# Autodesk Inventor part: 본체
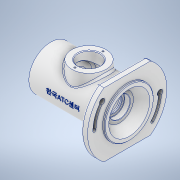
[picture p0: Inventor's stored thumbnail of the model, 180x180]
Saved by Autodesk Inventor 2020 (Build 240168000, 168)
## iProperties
Created: 2022-05
Part Number: 본체
Material: 알루미늄 6061
Document SubType Name: Modeling
Designer: Student
Density: 2.7 g/cm^3
Appearance: 알루미늄 - 평지
Mass: 692.617 g
Surface Area: 620.9 cm^2
Volume: 256.525 cm^3
Author: Student
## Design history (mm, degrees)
sketch "스케치3"
  geometry: L1 (47, 33.985)-(47, -33.985); L2 (-47, 33.985)-(-47, -33.985); A1 r 58 centre (0, 0) between (47, 33.985) and (-47, 33.985); A2 r 58 centre (0, 0) between (-47, -33.985) and (47, -33.985); 1 further point
  constraints: 4 end point, 4 point on circle, 2 centre point, 1 coincident, 1 parallel, 1 vertical
  dimensions: "d1" = 94 distance between parallel lines of L2 L1; "d2" = 47 horizontal distance of L1.start point (0, 0); "d3" = 58 radius of A2; "d4" = 58 radius of A1
extrude "돌출1" new body sketch "스케치3" distance "d5" = 10; taper "d6" = 0 deg
sketch "스케치4"
  geometry: C1 r 32 at (0, 0); 1 further point
  constraints: 1 centre point, 1 coincident
  dimensions: "d7" = 32 radius of C1
extrude "돌출2" join sketch "스케치4" distance "d8" = 102; taper "d9" = 0 deg
sketch "스케치6"
  geometry: C1 r 36 at (0, 0); 1 further point
  constraints: 1 centre point, 1 coincident
  dimensions: "d25" = 72 diameter of C1
extrude "돌출3" join sketch "스케치6" distance "d26" = 3; taper "d27" = 0 deg
sketch "스케치7"
  geometry: L1 (-118.309, 0)-(16.901, 0); L2 (0, -47)-(-10, -47) reference; L3 (-104, 0)-(-104, 24); L4 (-104, 24)-(-101, 24); L5 (-101, 24)-(-101, 22.5); L6 (-101, 22.5)-(-90, 22.5); L7 (-90, 22.5)-(-90, 17.5); L8 (-90, 17.5)-(-88.25, 17.5); L9 (-88.25, 17.5)-(-88.25, 18.5); L10 (-88.25, 18.5)-(-86, 18.5); L11 (-86, 18.5)-(-86, 17.5); L12 (-86, 17.5)-(-75, 17.5); L13 (-75, 17.5)-(-75, 27); L14 (-75, 27)-(-37, 27); L15 (3, -36)-(3, 36) reference; L16 (-26, 15)-(-21, 15); L17 (-21, 15)-(-21, 11); L18 (-21, 11)-(-19, 11); L19 (-19, 11)-(-19, 15); L20 (-11, 20)-(3, 30); L21 (-37, 27)-(-37, 17.5); L22 (-37, 17.5)-(-26, 17.5); L23 (-26, 17.5)-(-26, 15); L24 (-19, 15)-(-11.7, 15); L25 (-11.7, 15)-(-11, 15); L26 (-11, 15)-(-11, 20); 2 further points
  constraints: 48 end point, 14 perpendicular, 4 horizontal, 4 point on line, 3 vertical
  dimensions: "d28" = 47 distance between parallel lines of L2 L1; "d29" = 3 distance of L3.end L4.end; "d30" = 11 distance of L5.end L6.end; "d31" = 48 diameter of L4 L1; "d32" = 45 diameter of L6 L1; "d33" = 35 diameter of L8 L1; "d34" = 4 horizontal distance of L10.end L7.end; "d35" = 1.75 distance of L7.end L8.end; "d36" = 11 distance of L11.end L12.end; "d37" = 54 diameter of L14 L1; "d38" = 38 distance of L13.end L14.end; "d40" = 11 distance of L21.end L22.end; "d41" = 35 diameter of L22 L1; "d42" = 5 distance of L16.start L16.end; "d46" = 7.3 distance of L19.end L24.end; "d47" = 2 distance of L17.end L18.end; "d48" = 30 diameter of L24 L1; "d49" = 60 diameter of L20.end L1; "d50" = 40 diameter of L20.start L1; "d51" = 22 diameter of L18 L1; "d52" = 30 diameter of L16 L1; "d53" = 0.7 distance of L24.end L25.end; "d54" = 14 horizontal distance of L20.end L20.start; "d55" = 37 diameter of L10 L1
revolve "회전1" sketch "스케치7" stored, may be unused: angle "d56" = 90 deg
fillet "모깎기1" dims "d57" = 3
fillet "모깎기2" dims "d58" = 0.6, "d59" = 0.5
chamfer "모따기1" distance "d60" = 0.7; stored, may be unused: second distance "d61" = 2, angle "d62" = 30 deg
chamfer "모따기2" distance "d63" = 1; stored, may be unused: second distance "d64" = 2, angle "d65" = 45 deg
sketch "스케치8"
  geometry: C1 r 32 at (0, 0) reference; 1 further point
hole "구멍1" sketch "스케치8" at (0, 0) diameter "d66" = 43.376; stored, may be unused: countersink angle "d70" = 90 deg, drill point angle "d72" = 0 deg; dims "d67" = 8, "d68" = 4, "d69" = 2, "d71" = 8
node "작업 평면1"
sketch "스케치9"
  geometry: L1 (112, -32)-(112, 32) reference; L2 (112, 0)-(56, 0); C1 r 25 at (56, 0); C2 r 16 at (56, 0); 1 further point
  constraints: 2 centre point, 2 end point, 1 coincident, 1 horizontal, 1 midpoint
  dimensions: "d74" = 25 radius of C1; "d75" = 16 radius of C2; "d76" = 56 distance from line of L1 C1.centre
extrude "돌출4" join sketch "스케치9" stored distance "d77" = 3; taper "d78" = 0 deg; dims "d25" = 72
extrude "돌출5" cut sketch "스케치9" stored distance "d79" = 3; taper "d80" = 0 deg
feature "면 기울기1" dims angle "d81" = 5 deg
chamfer "모따기3" distance "d82" = 1; stored, may be unused: second distance "d83" = 2, angle "d84" = 45 deg
fillet "모깎기3" dims "d85" = 3
chamfer "모따기4" distance "d86" = 1; stored, may be unused: second distance "d87" = 2, angle "d88" = 45 deg
sketch "스케치10"
  geometry: L1 (0, 0)-(-48, 0); L2 (0, 0)-(-36.77, -30.854); L3 (36.77, 30.854)-(0, 0); L4 (0, 0)-(48, 0); A1 r 48 centre (0, 0) between (48, 0) and (36.77, 30.854); A2 r 52 centre (0, 0) between (52, 0) and (39.834, 33.425); A3 r 44 centre (0, 0) between (44, 0) and (33.706, 28.283); A4 r 4 centre (48, 0) between (44, 0) and (52, 0); A5 r 4 centre (36.77, 30.854) between (39.834, 33.425) and (33.706, 28.283); A6 r 48 centre (0, 0) between (-48, 0) and (-36.77, -30.854); A7 r 52 centre (0, 0) between (-52, 0) and (-39.834, -33.425); A8 r 44 centre (0, 0) between (-44, 0) and (-33.706, -28.283); A9 r 4 centre (-48, 0) between (-44, 0) and (-52, 0); A10 r 4 centre (-36.77, -30.854) between (-39.834, -33.425) and (-33.706, -28.283); A11 r 4 centre (36.77, 30.854) between (37.033, 26.862) and (40.58, 29.636); A12 r 4 centre (-48, 0) between (-45.636, -3.227) and (-50.136, -3.382); A13 r 48 centre (0, 0) between (48, 0) and (36.77, 30.854); A14 r 50.25 centre (0, 0) between (50.25, 0) and (40.58, 29.636); A15 r 45.75 centre (0, 0) between (45.75, 0) and (37.033, 26.862); A16 r 2.25 centre (48, 0) between (45.75, 0) and (50.25, 0); A17 r 48 centre (0, 0) between (-48, 0) and (-36.77, -30.854); A18 r 50.25 centre (0, 0) between (-50.136, -3.382) and (-38.494, -32.3); A19 r 45.75 centre (0, 0) between (-45.636, -3.227) and (-35.047, -29.408); A20 r 2.25 centre (-36.77, -30.854) between (-38.494, -32.3) and (-35.047, -29.408); 8 further points
  constraints: 41 point on circle, 20 centre point, 12 tangent, 8 end point, 6 coincident, 2 horizontal, 1 concentric, 1 other
  dimensions: "d95" = 48 radius of A6; "d96" = 4 radius of A4; "d99" = 40 deg angle of L2 L1; "d101" = 48 distance of L4.end L1.start; "d102" = 40 deg angle of L4 L3; "d103" = 4 radius of A11; "d104" = 4 radius of A12; "d126" = 2.25 radius of A16; "d127" = 2.25 radius of A20
extrude "돌출6" cut sketch "스케치10" distance "d105" = 4.4; taper "d106" = 0 deg
extrude "돌출7" cut sketch "스케치10" stored distance "d107" = 4.4; taper "d108" = 0 deg
extrude "돌출8" cut sketch "스케치10" extent not by distance; stored distance "d128" = 0; taper "d129" = 0 deg
sketch "스케치14"
  geometry: L1 (-112, 32)-(-112, -32) reference; C1 r 17 at (-56, 0) reference; 2 further points
  dimensions: "d131" = 56 distance from line of L1 point (-56, 20.5); "d132" = 20.5 distance of C1.centre point (-56, 20.5)
hole "구멍2" sketch "스케치14" at (-56, 20.5) diameter "d133" = 2.459; stored, may be unused: countersink angle "d137" = 90 deg, drill point angle "d139" = 118 deg; dims "d134" = 6, "d135" = 4, "d136" = 2, "d138" = 8
node "작업 평면2"
sketch "스케치15"
  geometry: L1 (0, -47)-(0, 47) reference; 3 further points
  constraints: 1 horizontal alignment, 1 midpoint, 1 other
  dimensions: "d144" = 62 distance from line of L1 point (-62, 0)
feature "엠보싱1" sketch "스케치15" dims "d145" = 0.5, "d146" = 0
chamfer "모따기5" distance "d147" = 0.7; stored, may be unused: second distance "d148" = 2, angle "d149" = 30 deg
node "솔리드1"
pattern_circular "원형 패턴1" dims angle "d141" = 360 deg
feature "A9D066F2-1C7D-4E18-AEED-F7BC21143FA4" dims "d66" = 43.376, "d67" = 8, "d68" = 4, "d69" = 2, "d70" = 90 deg, "d71" = 8, "d72" = 0
other parameters: "d0" = 116, "d73" = 38, "d143" = 57.5
